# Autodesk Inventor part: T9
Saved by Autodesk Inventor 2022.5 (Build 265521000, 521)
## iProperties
Created: 2025-02
Part Number: T9
Material: Generic
Document SubType Name: Modeling
Designer: AdminForWorker
Density: 1 g/cm^3
Appearance: Default
Title: T9
Author: AdminForWorker
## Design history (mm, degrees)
feature "T9"
body "Solid1"
